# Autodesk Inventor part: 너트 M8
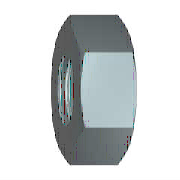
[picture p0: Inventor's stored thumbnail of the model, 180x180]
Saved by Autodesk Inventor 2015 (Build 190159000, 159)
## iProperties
IsCustomPart: 1
Created: 2012-02
Part Number: 너트 M8
Material: 강철, 연강
Description: 6각 너트 및 6각 가는 너트
Document SubType Name: Modeling
Standard: KS B 1012
Designer: mduedu
Standards Organization: KS
Language: ko-KR
Size Designation: M 8
Categories: <MemberInstance><Categories><Category DisplayName="조임쇠" InternalName="e4da775c-781d-43d5-af7c-5136215cf5a6" Mnemonic="FSTN"><Category DisplayName="너트" InternalN
Density: 7.86 g/cm^3
Mass: 4.30432 g
Surface Area: 5.27675 cm^2
Volume: 0.547623 cm^3
Appearance: 강철
Author: mduedu
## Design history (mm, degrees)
sketch "스케치1"
  geometry: L1 (-7.506, 0)-(-3.753, 6.5); L2 (-3.753, 6.5)-(3.753, 6.5); L3 (3.753, 6.5)-(7.506, 0); L4 (7.506, 0)-(3.753, -6.5); L5 (3.753, -6.5)-(-3.753, -6.5); L6 (-3.753, -6.5)-(-7.506, 0); 2 further points
  constraints: 12 end point, 1 coincident, 1 horizontal, 11 other
  dimensions: "d0" = 15.01111 distance of L3.end L1.start (= 1.1547 x SW)
extrude "본체" new body sketch "스케치1" distance "d1" = 5 (= KOH); taper "d2" = 0 deg
sketch "스케치2"
  geometry: L1 (0, 3.753)-(0, 7.506) reference; L2 (0, 7.506)-(5, 7.506) reference; L3 (5, 3.753)-(5, 7.506) reference; L4 (-1, 0)-(6, 0) reference; L5 (0.581, 7.506)-(0, 6.5); L6 (4.419, 7.506)-(5, 6.5)
  constraints: 4 end point, 4 point on line
  dimensions: "d3" = 30 deg angle of L1 L5 (= ANG1); "d4" = 30 deg angle of L3 L6 (= ANG2); "d5" = 13 diameter of L5.end L4 (= SW0); "d6" = 13 diameter of L6.end L4 (= SW01)
revolve "모따기1" sketch "스케치2" stored, may be unused: angle "d7" = 90 deg
sketch "스케치3"
  geometry: A1 r 6.5 centre (0, 0) between (-3.25, -5.629) and (3.25, -5.629) reference; 1 further point
  constraints: 1 coincident
hole "스레드" sketch "스케치3" at (0, 0) diameter "d25" = 6.647; stored, may be unused: countersink angle "d29" = 82 deg, drill point angle "d31" = 118 deg; dims "d26" = 6, "d27" = 4, "d28" = 2, "d30" = 8
workaxis "Work Axis1"
workplane "Work Plane1"
body "Solid1"
chamfer "모따기2" distance "d8" = 0.67658 (= -0.5 x GD1 + 0.5 x NND); stored, may be unused: angle "d9" = 30 deg, second distance "d40" = 0.67658 (= -0.5 x GD1 + 0.5 x NND)
chamfer "모따기3" distance "d10" = 0.67658 (= -0.5 x GD1 + 0.5 x NND); stored, may be unused: angle "d11" = 30 deg, second distance "d41" = 0.67658 (= -0.5 x GD1 + 0.5 x NND)
other parameters: "ANG1" = 30 deg [user parameter; used in 1 equation term], "ANG2" = 30 deg [user parameter; used in 1 equation term], "NND" = 8 [user parameter; used in 4 equation terms], "KOH" = 5 [user parameter; used in 1 equation term], "SW" = 13 [user parameter; used in 4 equation terms], "SW0" = 13 (= SW) [user parameter; used in 1 equation term], "SW01" = 13 (= SW) [user parameter; used in 1 equation term], "GD1" = 6.64684 (computed from THREADDIA, PTC, TOA) [user parameter; used in 4 equation terms], "d13" = 0, "d14" = 0, "d39" = 0, "d42" = 0, "GUL" = 0.67658 (= 0.541266 x PTC) [user parameter], "TPU" = 8 (computed from PTC) [user parameter], "THREADDIA" = 8 [user parameter; used in 1 equation term], "TOA" = 30 deg [user parameter; used in 1 equation term], "PTC" = 1.25 [user parameter; used in 4 equation terms], "E0" = 15.015 (= 1.155 x SW) [user parameter], "GAL" = 0.67658 (= 0.541266 x PTC) [user parameter]
